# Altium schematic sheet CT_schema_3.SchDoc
size 313 x 185 mm
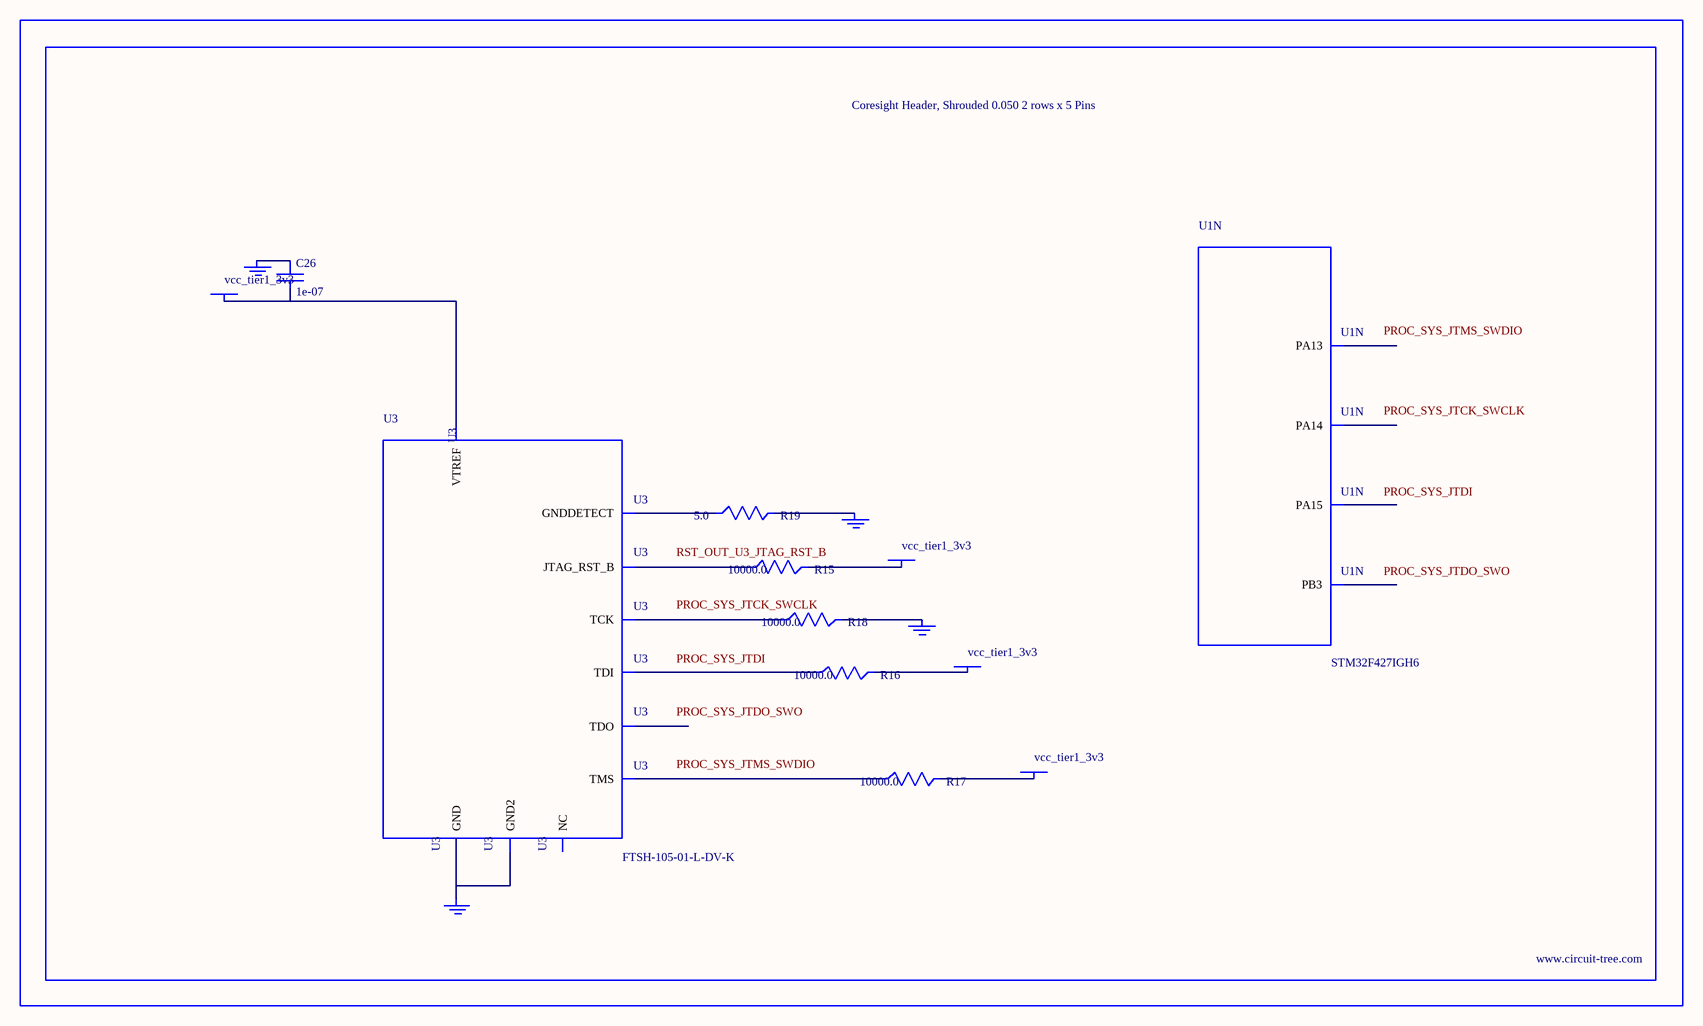
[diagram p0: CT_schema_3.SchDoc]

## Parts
BORDER2  (no value)
C26  1e-07  [C0402]
GND_INSTANCE_2_0  (no value)
GND_INSTANCE_2_1  (no value)
GND_INSTANCE_2_2  (no value)
GND_INSTANCE_2_3  (no value)
POWER_INSTANCE_2_0  vcc_tier1_3v3
POWER_INSTANCE_2_1  vcc_tier1_3v3
POWER_INSTANCE_2_2  vcc_tier1_3v3
POWER_INSTANCE_2_3  vcc_tier1_3v3
R15  10000.0  [R0603]
R16  10000.0  [R0603]
R17  10000.0  [R0603]
R18  10000.0  [R0603]
R19  5.0  [R0603]
U1  STM32F427IGH6  [UFBGA176_25]  (part N of 16)
U3  FTSH-105-01-L-DV-K  [SAMTEC_FTSH-105-01-L-DV-K]

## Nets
NetC26_1: C26.1 GND_INSTANCE_2_0.0(GND)
NetC26_2: C26.2 POWER_INSTANCE_2_0.0(PWR) U3.1(VTREF)
NetGND_INSTANCE_2_1_0: GND_INSTANCE_2_1.0(GND) R18.2
NetGND_INSTANCE_2_2_0: GND_INSTANCE_2_2.0(GND) R19.2
NetGND_INSTANCE_2_3_0: GND_INSTANCE_2_3.0(GND) U3.3(GND) U3.5(GND2)
NetPOWER_INSTANCE_2_1_0: POWER_INSTANCE_2_1.0(PWR) R17.2
NetPOWER_INSTANCE_2_2_0: POWER_INSTANCE_2_2.0(PWR) R16.2
NetPOWER_INSTANCE_2_3_0: POWER_INSTANCE_2_3.0(PWR) R15.2
NetR15_1: R15.1 U3.10(JTAG_RST_B)
NetR16_1: R16.1 U3.8(TDI)
NetR17_1: R17.1 U3.2(TMS)
NetR18_1: R18.1 U3.4(TCK)
NetR19_1: R19.1 U3.9(GNDDETECT)

Not connected (* = marked no-connect by the designer): U1 A10(PB3) A13(PA15) A14(PA14) A15(PA13); U3 6(TDO) 7(NC)

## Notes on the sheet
- Labels drawn without touching a wire or pin: PROC_SYS_JTCK_SWCLK, PROC_SYS_JTDI, PROC_SYS_JTDO_SWO, PROC_SYS_JTMS_SWDIO, RST_OUT_U3_JTAG_RST_B

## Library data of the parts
BORDER2 = BORDER_PAGE2
C26 = C0402C104K3RACTU
GND_INSTANCE_2_0-GND_INSTANCE_2_3 = GND
POWER_INSTANCE_2_0-POWER_INSTANCE_2_3 = PWR
R15-R18 = RC0603JR-0710KL
R19 = ERJ-3GEYJ5R1V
